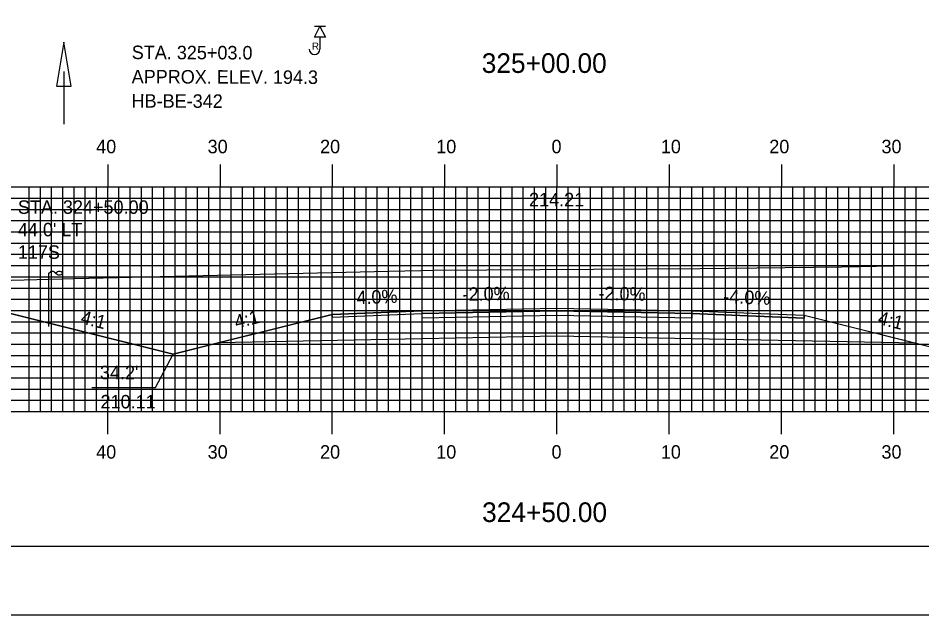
# Model space of a CAD drawing. Extents: x 1821211 to 1821555, y 442591 to 442811.
# Drawn here: x 1821329.2 to 1821409.7, y 442590.5 to 442643.7 of the extents above; entities that cross this region are included whole.
import ezdxf

# ---------------------------------------------------------------- set-up
doc = ezdxf.new("R2010")
doc.units = 0
for name, color, linetype in [('ANNOTATION', 7, 'Continuous'), ('BORDER', 7, 'Continuous'), ('BORING - REFUSAL', 7, 'Continuous'), ('D_Drainage_Ditch_Line', 7, 'Continuous'), ('D_Drainage_Text', 7, 'Continuous'), ('D_Roadway_Centerline', 7, 'Continuous'), ('D_Roadway_Centerline_Text', 7, 'Continuous'), ('D_Roadway_Edge_Shoulder', 7, 'Continuous'), ('D_Roadway_Edge_TW', 7, 'Continuous'), ('D_Roadway_Pavement', 7, 'Continuous'), ('D_Roadway_SlopeLines', 7, 'Continuous'), ('D_Roadway_SubGrade', 7, 'Continuous'), ('D_Utilities_Pole_Joint', 7, 'Continuous'), ('H_V ANNOTATION', 7, 'Continuous'), ('MAJOR', 7, 'Continuous'), ('MINOR', 7, 'Continuous'), ('PLOT BOUNDARY', 7, 'Continuous'), ('S_Roadway_Centerline', 7, 'Continuous')]:
    doc.layers.add(name, color=color, linetype=linetype)

msp = doc.modelspace()

# ---------------------------------------------------------------- linework, layer by layer
at = {"layer": 'ANNOTATION'}
msp.add_lwpolyline([(1821335.806, 442610.813), (1821341.498, 442610.813), (1821343.056, 442613.773)], dxfattribs=at)
at = {"layer": 'BORDER'}
msp.add_lwpolyline([(1821227.63, 442596.665), (1821547.63, 442596.665), (1821547.63, 442806.665), (1821227.63, 442806.665)], close=True, dxfattribs=at)
at = {"layer": 'BORING - REFUSAL'}
for p, q in [((1821356.61, 442642.965), (1821355.65, 442642.965)), ((1821356.13, 442642.006), (1821356.13, 442640.947))]:
    msp.add_line(p, q, dxfattribs=at)
msp.add_lwpolyline([(1821356.13, 442642.965), (1821356.61, 442642.006), (1821355.65, 442642.006)], close=True, dxfattribs=at)
msp.add_arc((1821355.645, 442640.947), 0.485, 180, 0, dxfattribs=at)
at = {"layer": 'D_Drainage_Ditch_Line'}
msp.add_line((1821333.316, 442638.944), (1821333.316, 442634.245), dxfattribs=at)
msp.add_lwpolyline([(1821332.66, 442637.632), (1821333.972, 442637.632), (1821333.316, 442641.569)], close=True, dxfattribs=at)
at = {"layer": 'D_Roadway_Centerline'}
msp.add_lwpolyline([(1821315.24, 442620.067), (1821316.49, 442620.043), (1821317.74, 442619.937), (1821318.99, 442619.748), (1821320.24, 442619.477), (1821343.056, 442613.773), (1821347.056, 442614.773), (1821357.23, 442617.317), (1821365.23, 442617.637), (1821377.23, 442617.877), (1821389.23, 442617.637), (1821399.23, 442617.237), (1821409.23, 442614.737), (1821413.23, 442613.737), (1821446.643, 442622.09), (1821447.893, 442622.37), (1821449.143, 442622.584), (1821450.393, 442622.732), (1821451.643, 442622.815)], dxfattribs=at)
at = {"layer": 'D_Roadway_Edge_Shoulder'}
for points in [[(1821365.23, 442617.637), (1821357.23, 442617.317), (1821357.23, 442617.067), (1821365.23, 442617.387)], [(1821389.23, 442617.637), (1821399.23, 442617.237), (1821399.23, 442616.987), (1821389.23, 442617.387)]]:
    msp.add_lwpolyline(points, close=True, dxfattribs=at)
at = {"layer": 'D_Roadway_Edge_TW'}
msp.add_lwpolyline([(1821365.23, 442617.387), (1821365.23, 442617.637), (1821377.23, 442617.877), (1821389.23, 442617.637), (1821389.23, 442617.387), (1821377.23, 442617.627)], close=True, dxfattribs=at)
at = {"layer": 'D_Roadway_Pavement'}
msp.add_lwpolyline([(1821365.23, 442616.97), (1821365.23, 442617.387), (1821377.23, 442617.627), (1821389.23, 442617.387), (1821389.23, 442616.97), (1821377.23, 442617.21)], close=True, dxfattribs=at)
at = {"layer": 'D_Roadway_SlopeLines'}
for points in [[(1821343.056, 442613.773), (1821320.24, 442619.477), (1821318.99, 442619.748), (1821317.74, 442619.937), (1821316.49, 442620.043), (1821315.24, 442620.067)], [(1821357.23, 442617.317), (1821343.056, 442613.773)], [(1821399.23, 442617.237), (1821413.23, 442613.737)]]:
    msp.add_lwpolyline(points, dxfattribs=at)
at = {"layer": 'D_Roadway_SubGrade'}
msp.add_lwpolyline([(1821365.23, 442615.137), (1821347.056, 442614.773), (1821357.23, 442617.317), (1821357.23, 442617.067), (1821365.23, 442617.387), (1821377.23, 442617.627), (1821389.23, 442617.387), (1821399.23, 442616.987), (1821399.23, 442617.237), (1821409.23, 442614.737), (1821389.23, 442615.137), (1821377.23, 442615.377)], close=True, dxfattribs=at)
at = {"layer": 'D_Utilities_Pole_Joint'}
for p, q in [((1821331.98, 442620.987), (1821332.136, 442621.098)), ((1821331.98, 442616.23), (1821331.98, 442620.987)), ((1821332.449, 442621.098), (1821332.605, 442620.987)), ((1821332.761, 442621.098), (1821332.605, 442620.987)), ((1821332.605, 442620.987), (1821332.761, 442620.877)), ((1821333.23, 442620.987), (1821333.074, 442621.098)), ((1821333.074, 442620.877), (1821333.23, 442620.987)), ((1821333.23, 442616.23), (1821333.23, 442620.987))]:
    msp.add_line(p, q, dxfattribs=at)
for centre, start, end in [((1821332.292, 442620.877), 90, 125.26439), ((1821332.292, 442620.877), 54.73561, 90), ((1821332.917, 442620.877), 90, 125.26439), ((1821332.917, 442621.098), 234.73561, 270), ((1821332.917, 442620.877), 54.73561, 90), ((1821332.917, 442621.098), 270, 305.26439)]:
    msp.add_arc(centre, 0.271, start, end, dxfattribs=at)
at = {"layer": 'MAJOR'}
for p, q in [((1821337.23, 442630.669), (1821337.23, 442628.665)), ((1821347.23, 442630.669), (1821347.23, 442628.665)), ((1821357.23, 442630.669), (1821357.23, 442628.665)), ((1821367.23, 442630.669), (1821367.23, 442628.665)), ((1821377.23, 442630.669), (1821377.23, 442628.665)), ((1821387.23, 442630.669), (1821387.23, 442628.665)), ((1821397.23, 442630.669), (1821397.23, 442628.665)), ((1821407.23, 442630.669), (1821407.23, 442628.665)), ((1821237.23, 442628.665), (1821517.23, 442628.665)), ((1821237.23, 442628.665), (1821517.23, 442628.665)), ((1821337.23, 442608.665), (1821337.23, 442628.665)), ((1821347.23, 442608.665), (1821347.23, 442628.665)), ((1821357.23, 442608.665), (1821357.23, 442628.665)), ((1821367.23, 442608.665), (1821367.23, 442628.665)), ((1821377.23, 442608.665), (1821377.23, 442628.665)), ((1821387.23, 442608.665), (1821387.23, 442628.665)), ((1821397.23, 442608.665), (1821397.23, 442628.665)), ((1821407.23, 442608.665), (1821407.23, 442628.665)), ((1821237.23, 442623.665), (1821517.23, 442623.665)), ((1821237.23, 442618.665), (1821517.23, 442618.665)), ((1821237.23, 442613.665), (1821517.23, 442613.665)), ((1821237.23, 442608.665), (1821517.23, 442608.665)), ((1821237.23, 442608.665), (1821517.23, 442608.665)), ((1821337.23, 442606.661), (1821337.23, 442608.665)), ((1821347.23, 442606.661), (1821347.23, 442608.665)), ((1821357.23, 442606.661), (1821357.23, 442608.665)), ((1821367.23, 442606.661), (1821367.23, 442608.665)), ((1821377.23, 442606.661), (1821377.23, 442608.665)), ((1821387.23, 442606.661), (1821387.23, 442608.665)), ((1821397.23, 442606.661), (1821397.23, 442608.665)), ((1821407.23, 442606.661), (1821407.23, 442608.665))]:
    msp.add_line(p, q, dxfattribs=at)
at = {"layer": 'MINOR'}
for p, q in [((1821330.23, 442608.665), (1821330.23, 442628.665)), ((1821331.23, 442608.665), (1821331.23, 442628.665)), ((1821332.23, 442608.665), (1821332.23, 442628.665)), ((1821333.23, 442608.665), (1821333.23, 442628.665)), ((1821334.23, 442608.665), (1821334.23, 442628.665)), ((1821335.23, 442608.665), (1821335.23, 442628.665)), ((1821336.23, 442608.665), (1821336.23, 442628.665)), ((1821338.23, 442608.665), (1821338.23, 442628.665)), ((1821339.23, 442608.665), (1821339.23, 442628.665)), ((1821340.23, 442608.665), (1821340.23, 442628.665)), ((1821341.23, 442608.665), (1821341.23, 442628.665)), ((1821342.23, 442608.665), (1821342.23, 442628.665)), ((1821343.23, 442608.665), (1821343.23, 442628.665)), ((1821344.23, 442608.665), (1821344.23, 442628.665)), ((1821345.23, 442608.665), (1821345.23, 442628.665)), ((1821346.23, 442608.665), (1821346.23, 442628.665)), ((1821348.23, 442608.665), (1821348.23, 442628.665)), ((1821349.23, 442608.665), (1821349.23, 442628.665)), ((1821350.23, 442608.665), (1821350.23, 442628.665)), ((1821351.23, 442608.665), (1821351.23, 442628.665)), ((1821352.23, 442608.665), (1821352.23, 442628.665)), ((1821353.23, 442608.665), (1821353.23, 442628.665)), ((1821354.23, 442608.665), (1821354.23, 442628.665)), ((1821355.23, 442608.665), (1821355.23, 442628.665)), ((1821356.23, 442608.665), (1821356.23, 442628.665)), ((1821358.23, 442608.665), (1821358.23, 442628.665)), ((1821359.23, 442608.665), (1821359.23, 442628.665)), ((1821360.23, 442608.665), (1821360.23, 442628.665)), ((1821361.23, 442608.665), (1821361.23, 442628.665)), ((1821362.23, 442608.665), (1821362.23, 442628.665)), ((1821363.23, 442608.665), (1821363.23, 442628.665)), ((1821364.23, 442608.665), (1821364.23, 442628.665)), ((1821365.23, 442608.665), (1821365.23, 442628.665)), ((1821366.23, 442608.665), (1821366.23, 442628.665)), ((1821368.23, 442608.665), (1821368.23, 442628.665)), ((1821369.23, 442608.665), (1821369.23, 442628.665)), ((1821370.23, 442608.665), (1821370.23, 442628.665)), ((1821371.23, 442608.665), (1821371.23, 442628.665)), ((1821372.23, 442608.665), (1821372.23, 442628.665)), ((1821373.23, 442608.665), (1821373.23, 442628.665)), ((1821374.23, 442608.665), (1821374.23, 442628.665)), ((1821375.23, 442608.665), (1821375.23, 442628.665)), ((1821376.23, 442608.665), (1821376.23, 442628.665)), ((1821378.23, 442608.665), (1821378.23, 442628.665)), ((1821379.23, 442608.665), (1821379.23, 442628.665)), ((1821380.23, 442608.665), (1821380.23, 442628.665)), ((1821381.23, 442608.665), (1821381.23, 442628.665)), ((1821382.23, 442608.665), (1821382.23, 442628.665)), ((1821383.23, 442608.665), (1821383.23, 442628.665)), ((1821384.23, 442608.665), (1821384.23, 442628.665)), ((1821385.23, 442608.665), (1821385.23, 442628.665)), ((1821386.23, 442608.665), (1821386.23, 442628.665)), ((1821388.23, 442608.665), (1821388.23, 442628.665)), ((1821389.23, 442608.665), (1821389.23, 442628.665)), ((1821390.23, 442608.665), (1821390.23, 442628.665)), ((1821391.23, 442608.665), (1821391.23, 442628.665)), ((1821392.23, 442608.665), (1821392.23, 442628.665)), ((1821393.23, 442608.665), (1821393.23, 442628.665)), ((1821394.23, 442608.665), (1821394.23, 442628.665)), ((1821395.23, 442608.665), (1821395.23, 442628.665)), ((1821396.23, 442608.665), (1821396.23, 442628.665)), ((1821398.23, 442608.665), (1821398.23, 442628.665)), ((1821399.23, 442608.665), (1821399.23, 442628.665)), ((1821400.23, 442608.665), (1821400.23, 442628.665)), ((1821401.23, 442608.665), (1821401.23, 442628.665)), ((1821402.23, 442608.665), (1821402.23, 442628.665)), ((1821403.23, 442608.665), (1821403.23, 442628.665)), ((1821404.23, 442608.665), (1821404.23, 442628.665)), ((1821405.23, 442608.665), (1821405.23, 442628.665)), ((1821406.23, 442608.665), (1821406.23, 442628.665)), ((1821408.23, 442608.665), (1821408.23, 442628.665)), ((1821409.23, 442608.665), (1821409.23, 442628.665)), ((1821237.23, 442627.665), (1821517.23, 442627.665)), ((1821237.23, 442626.665), (1821517.23, 442626.665)), ((1821237.23, 442625.665), (1821517.23, 442625.665)), ((1821237.23, 442624.665), (1821517.23, 442624.665)), ((1821237.23, 442622.665), (1821517.23, 442622.665)), ((1821237.23, 442621.665), (1821517.23, 442621.665)), ((1821237.23, 442620.665), (1821517.23, 442620.665)), ((1821237.23, 442619.665), (1821517.23, 442619.665)), ((1821237.23, 442617.665), (1821517.23, 442617.665)), ((1821237.23, 442616.665), (1821517.23, 442616.665)), ((1821237.23, 442615.665), (1821517.23, 442615.665)), ((1821237.23, 442614.665), (1821517.23, 442614.665)), ((1821237.23, 442612.665), (1821517.23, 442612.665)), ((1821237.23, 442611.665), (1821517.23, 442611.665)), ((1821237.23, 442610.665), (1821517.23, 442610.665)), ((1821237.23, 442609.665), (1821517.23, 442609.665))]:
    msp.add_line(p, q, dxfattribs=at)
at = {"layer": 'PLOT BOUNDARY'}
msp.add_lwpolyline([(1821211.443, 442590.547), (1821551.443, 442590.547), (1821551.443, 442810.547), (1821211.443, 442810.547)], close=True, dxfattribs=at)
at = {"layer": 'S_Roadway_Centerline'}
msp.add_lwpolyline([(1821320.8, 442620.145), (1821334.263, 442620.498), (1821362.26, 442621.167), (1821365.109, 442621.232), (1821366.238, 442621.252), (1821389.976, 442621.415), (1821402.595, 442621.565), (1821430.067, 442622.082), (1821433.211, 442622.218), (1821435.001, 442622.15), (1821456.903, 442623.025), (1821466.505, 442622.848), (1821472.997, 442623.015), (1821482.642, 442622.686), (1821490.543, 442622.39), (1821507.176, 442622.779), (1821517.073, 442622.836), (1821517.23, 442622.832)], dxfattribs=at)

# ---------------------------------------------------------------- texts
at = {"layer": 'ANNOTATION'}
for s, rotation, p in [('-4.0%', 2.29061, (1821358.862, 442618.184)), ('-2.0%', 1.14576, (1821368.836, 442618.509)), ('-2.0%', 358.85424, (1821380.916, 442618.603)), ('-4.0%', 357.70939, (1821392.022, 442618.327)), ('4:1', 345.96376, (1821334.748, 442616.528)), ('4:1', 14.03624, (1821348.679, 442616.04)), ('4:1', 345.96376, (1821405.736, 442616.472))]:
    msp.add_text(s, height=1.2, rotation=rotation, dxfattribs=at).set_placement(p)
for s, p in [("34.2'", (1821336.541, 442611.539)), ('210.11', (1821336.589, 442608.939))]:
    msp.add_text(s, height=1.2, dxfattribs=at).set_placement(p)
at = {"layer": 'BORING - REFUSAL'}
for s, p in [('STA. 325+03.0', (1821339.369, 442640.053)), ('APPROX. ELEV. 194.3', (1821339.362, 442637.893)), ('HB-BE-342', (1821339.355, 442635.733))]:
    msp.add_text(s, height=1.2, rotation=359.81416, dxfattribs=at).set_placement(p)
msp.add_text('R', height=0.64, dxfattribs=at).set_placement((1821355.421, 442640.891))
at = {"layer": 'D_Drainage_Text'}
for s, p in [('STA. 324+50.00', (1821329.229, 442626.272)), ("44.0' LT", (1821329.229, 442624.268)), ('117S', (1821329.229, 442622.264))]:
    msp.add_text(s, height=1.2, dxfattribs=at).set_placement(p)
at = {"layer": 'D_Roadway_Centerline'}
for s, p in [('C', (1821377.225, 442617.877)), ('L', (1821377.23, 442617.869))]:
    msp.add_text(s, height=0.0146, dxfattribs=at).set_placement(p)
at = {"layer": 'D_Roadway_Centerline_Text'}
msp.add_text('214.21', height=1.2, dxfattribs=at).set_placement((1821374.747, 442626.941))
at = {"layer": 'H_V ANNOTATION'}
for s, height, p in [('325+00.00', 1.75, (1821370.535, 442638.821)), ('40', 1.2, (1821336.202, 442631.665)), ('30', 1.2, (1821346.127, 442631.665)), ('20', 1.2, (1821356.138, 442631.665)), ('10', 1.2, (1821366.481, 442631.665)), ('0', 1.2, (1821376.748, 442631.665)), ('10', 1.2, (1821386.481, 442631.665)), ('20', 1.2, (1821396.138, 442631.665)), ('30', 1.2, (1821406.127, 442631.665)), ('40', 1.2, (1821336.202, 442604.465)), ('30', 1.2, (1821346.127, 442604.465)), ('20', 1.2, (1821356.138, 442604.465)), ('10', 1.2, (1821366.481, 442604.465)), ('0', 1.2, (1821376.748, 442604.465)), ('10', 1.2, (1821386.481, 442604.465)), ('20', 1.2, (1821396.138, 442604.465)), ('30', 1.2, (1821406.127, 442604.465)), ('324+50.00', 1.75, (1821370.566, 442598.821))]:
    msp.add_text(s, height=height, dxfattribs=at).set_placement(p)

doc.saveas('drawing.dxf')
